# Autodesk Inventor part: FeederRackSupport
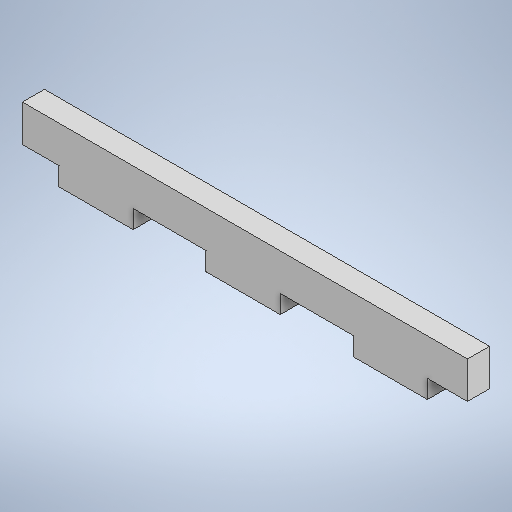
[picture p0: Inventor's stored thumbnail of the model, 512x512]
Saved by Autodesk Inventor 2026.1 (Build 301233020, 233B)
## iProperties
Created: 2026-11
Part Number: FeederRackSupport
Material: Generic
Document SubType Name: Modeling
Designer: hp
Density: 1 g/cm^3
Appearance: Default
Author: hp
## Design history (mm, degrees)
sketch "Sketch3"
  geometry: L1 (0, 0)-(121, 0); L2 (121, 0)-(121, 10); L3 (121, 10)-(0, 10); L4 (0, 10)-(0, 0); L5 (0, 0)-(121, 0); L6 (121, 0)-(121, -5); L7 (121, -5)-(0, -5); L8 (0, -5)-(0, 0)
  constraints: 16 end point, 4 parallel, 2 horizontal, 2 perpendicular, 1 point on line
  dimensions: "d3" = 121 distance of L3.end L2.end; "d4" = 10 distance of L2.end L1.end; "d5" = 5 distance of L5.end L6.end
extrude "Extrusion1" new body sketch "Sketch3" distance "d6" = 6; taper "d7" = 0 deg
sketch "Sketch4"
  geometry: L1 (0, 0)-(121, 0) reference; L2 (0, -5)-(0, 0) reference; L3 (121, -5)-(0, -5) reference; L4 (121, 0)-(121, -5) reference; L5 (10, 0)-(30, 0); L6 (30, 0)-(30, -5); L7 (30, -5)-(10, -5); L8 (10, -5)-(10, 0); L9 (9.9, 0)-(30.1, 0); L10 (30.1, 0)-(30.1, -5); L11 (30.1, -5)-(9.9, -5); L12 (9.9, -5)-(9.9, 0); L13 (50, 0)-(70, 0); L14 (70, 0)-(70, -5); L15 (70, -5)-(50, -5); L16 (50, -5)-(50, 0); L17 (49.9, 0)-(70.1, 0); L18 (70.1, 0)-(70.1, -5); L19 (70.1, -5)-(49.9, -5); L20 (49.9, -5)-(49.9, 0); L21 (90, 0)-(110, 0); L22 (110, 0)-(110, -5); L23 (110, -5)-(90, -5); L24 (90, -5)-(90, 0); L25 (89.9, 0)-(110.1, 0); L26 (110.1, 0)-(110.1, -5); L27 (110.1, -5)-(89.9, -5); L28 (89.9, -5)-(89.9, 0); 6 further points
  constraints: 48 end point, 6 point on line, 4 parallel, 3 horizontal, 2 midpoint, 2 perpendicular, 1 coincident, 36 other
  dimensions: "d8" = 20 distance of L6.end L7.end; "d9" = 10 distance between parallel lines of L2 L8; "d10" = 20.2 distance of L10.end L11.end; "d13" = 40 distance of L5.start L13.start
extrude "Extrusion2" join sketch "Sketch4" stored distance "d18" = 6; taper "d19" = 0 deg
body "Solid1"
node "Sketch Rectangular Pattern1" dims "d13" = 40, "d16" = 10
